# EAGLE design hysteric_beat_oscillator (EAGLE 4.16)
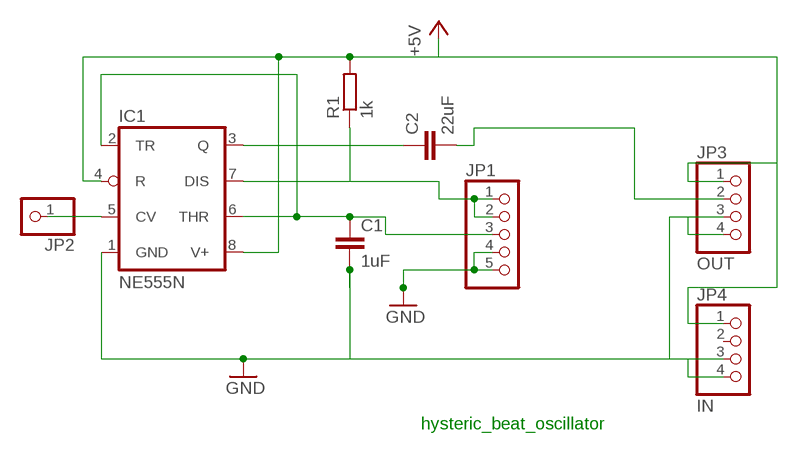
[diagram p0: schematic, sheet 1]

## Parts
C1  1uF  C-EU025-024X044  [C025-024X044]
C2  22uF  C-EU025-024X044  [C025-024X044]
IC1  NE555N  [DIL08]
JP1  PINHD-1X5  [1X05]
JP2  PINHD-1X1  [1X01]
JP3  OUT  PINHD-1X4  [1X04]
JP4  IN  PINHD-1X4  [1X04]
R1  1k  R-EU_0207/7  [0207/7]

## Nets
+5V: IC1.4(R) IC1.8(V+) JP3.1 JP4.1 R1.2
GND: C1.2 IC1.1(GND) JP1.4 JP1.5 JP3.3 JP3.4 JP4.3 JP4.4
N$1: IC1.7(DIS) JP1.1 JP1.2 R1.1
N$2: IC1.5(CV) JP2.1
N$3: C2.1 IC1.3(Q)
N$4: C1.1 IC1.2(TR) IC1.6(THR) JP1.3
OUT: C2.2 JP3.2
Unconnected: JP4.2

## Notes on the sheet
- hysteric_beat_oscillator

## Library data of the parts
C1 C2 = rcl:C-EU: CAPACITOR, European symbol
IC1 = linear:*555: TIMER
JP1 = pinhead:PINHD-1X5: PIN HEADER
JP2 = pinhead:PINHD-1X1: PIN HEADER
JP3 JP4 = pinhead:PINHD-1X4: PIN HEADER
R1 = rcl:R-EU_: RESISTOR, European symbol

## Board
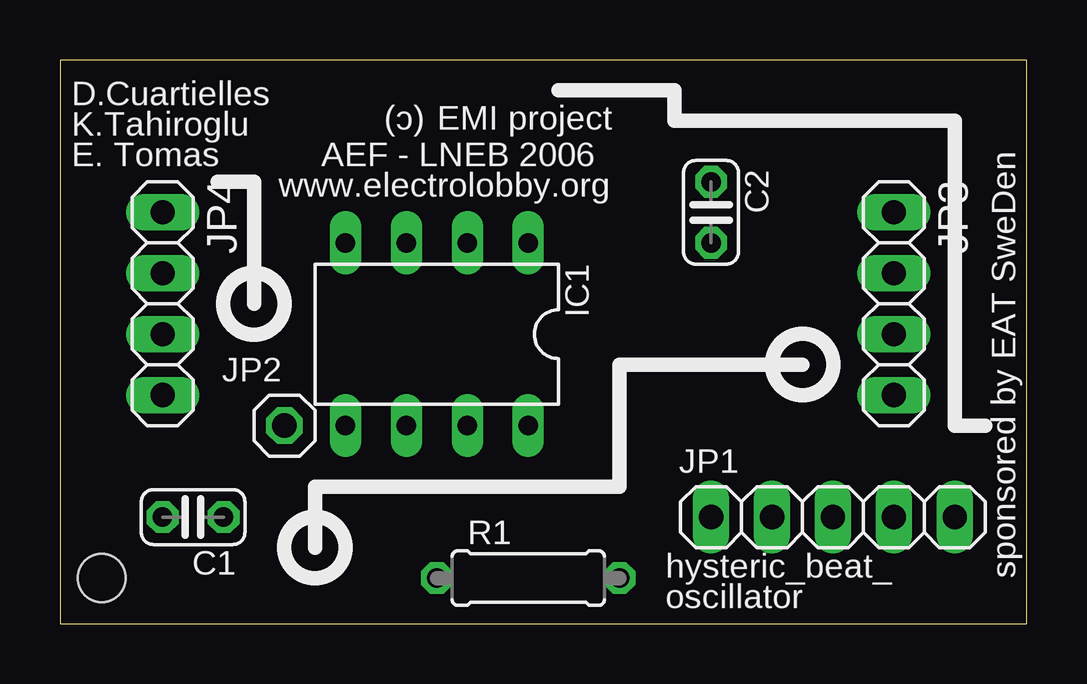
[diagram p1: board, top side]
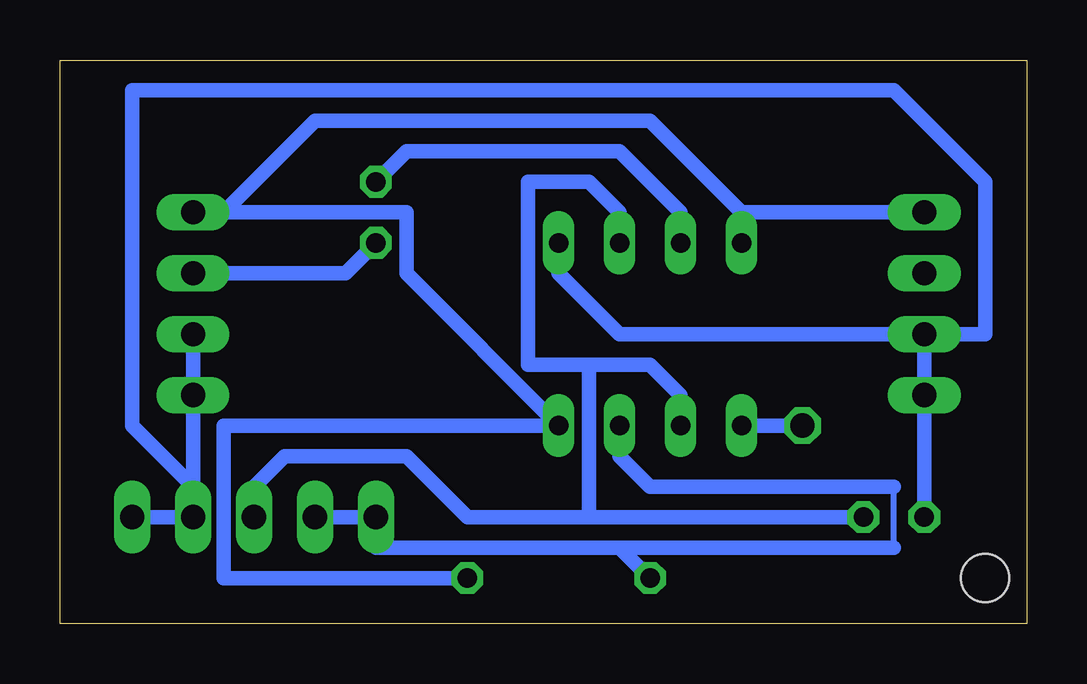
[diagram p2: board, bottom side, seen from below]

Size 40.31 x 23.48 mm. Coordinates in mm from the lower left corner, seen from the top.
Outline: 0,0 40.31,0 40.31,23.48 0,23.48 0,0
Copper layers (1*16): Top 0.035mm / dielectric 1.5mm / Bottom 0.035mm
Design rules "default": minimum track width 10mil, minimum drill 24mil, track to track 8mil, track to pad 8mil, pad to pad 8mil, via to via 8mil, smd to smd 8mil, copper to edge 40mil, drill to drill 8mil, minimum pad ring 10mil, minimum via ring 8mil, stop-mask expansion 4mil, vias tented up to drill 0mil, thermal gap 10mil
Holes 2 mm at 1.74,1.9

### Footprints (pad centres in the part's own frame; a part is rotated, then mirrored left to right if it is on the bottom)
C025-024X044 = drill 0.813 octagon: 1 -1.27,0; 2 1.27,0
DIL08 = drill 0.813 long: 1 -3.81,-3.81; 2 -1.27,-3.81; 3 1.27,-3.81; 4 3.81,-3.81; 5 3.81,3.81; 6 1.27,3.81; 7 -1.27,3.81; 8 -3.81,3.81
1X05 = drill 1.016 long: 1 -5.08,0; 2 -2.54,0; 3 0,0; 4 2.54,0; 5 5.08,0
1X01 = drill 1.016 octagon: 1 0,0
1X04 = drill 1.016 long: 1 -3.81,0; 2 -1.27,0; 3 1.27,0; 4 3.81,0
0207/7 = drill 0.813 octagon: 1 -3.81,0; 2 3.81,0

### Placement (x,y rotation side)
C1  5.55,4.44 180 top
C2  27.14,17.14 270 top
IC1  15.71,12.06 180 top
JP1  32.22,4.44 0 top
JP2  9.36,8.25 0 top
JP3  34.76,13.33 270 top
JP4  4.28,13.33 270 top
R1  19.52,1.9 0 top

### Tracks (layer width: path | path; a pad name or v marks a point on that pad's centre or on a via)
+5V
  Bottom 0.61: R1.2 33.49,1.9 33.49,8.25 IC1.8 25.87,14.6 25.87,17.14 33.49,17.14 | JP4.1 11.9,17.14 | 33.49,17.14 29.68,20.95 15.71,20.95 11.9,17.14 | 11.9,17.14 IC1.4 | 33.49,17.14 JP3.1
GND
  Bottom 0.61: JP1.5 JP1.4 34.76,5.71 | JP3.3 JP3.4 34.76,5.71 | C1.2 JP4.4 JP4.3 | IC1.1 19.52,14.6 16.98,12.06 JP4.3 | 34.76,5.71 37.3,8.25 37.3,22.22 5.55,22.22 1.74,18.41 1.74,12.06 JP4.3
N$1
  Bottom 0.254: 5.55,3.17 5.55,5.71
  Bottom 0.61: 16.98,3.17 R1.1 | 16.98,3.17 27.14,3.17 JP1.1 JP1.2 | 5.55,5.71 15.71,5.71 16.98,6.98 IC1.7 | 5.55,3.17 16.98,3.17
N$2
  Bottom 0.61: JP2.1 IC1.5
N$3
  Bottom 0.61: C2.1 25.87,19.68 16.98,19.68 14.44,17.14 IC1.3
N$4
  Bottom 0.61: 18.25,4.44 23.33,4.44 25.87,6.98 30.95,6.98 32.22,5.71 JP1.3 | C1.1 18.25,4.44 | 18.25,10.79 15.71,10.79 14.44,9.52 IC1.6 | 18.25,4.44 18.25,10.79 | 18.25,10.79 20.79,10.79 20.79,18.41 18.25,18.41 16.98,17.14 IC1.2
OUT
  Bottom 0.61: C2.2 28.41,14.6 JP3.2

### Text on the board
tPlace: D.Cuartielles | (c) | EMI project | K.Tahiroglu | E. Tomas | AEF - LNEB 2006 | www.electrolobby.org | hysteric_beat_ | sponsored by EAT SweDen | oscillator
